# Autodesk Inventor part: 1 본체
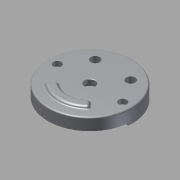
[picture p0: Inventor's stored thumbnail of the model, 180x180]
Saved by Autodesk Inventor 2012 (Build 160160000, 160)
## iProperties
Created: 2015-04
Part Number: 1 본체
Material: Default
Document SubType Name: Modeling
Designer: Owner
Density: 1 g/cm^3
Author: Owner
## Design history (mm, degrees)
sketch "스케치1"
  geometry: C1 r 95 at (0, 0); 1 further point
  constraints: 1 centre point, 1 coincident
  dimensions: "d2" = 190 diameter of C1
extrude "돌출1" new body sketch "스케치1" distance "d3" = 7; taper "d4" = 0 deg
sketch "스케치14"
  geometry: L1 (-82.104, 12)-(-47.117, 12); L2 (47.117, 12)-(82.104, 12); A1 r 95 centre (0, 0) between (-91.763, 24.588) and (91.763, 24.588) reference; A2 r 42 centre (0, 0) between (38.056, 17.769) and (-38.056, 17.769); A3 r 10 centre (47.117, 22) between (38.056, 17.769) and (47.117, 12); A4 r 10 centre (82.104, 22) between (82.104, 12) and (91.763, 24.588); A5 r 10 centre (-47.117, 22) between (-47.117, 12) and (-38.056, 17.769); A6 r 10 centre (-82.104, 22) between (-91.763, 24.588) and (-82.104, 12)
  constraints: 12 point on circle, 12 tangent, 5 centre point, 4 end point, 3 equal radius, 2 horizontal, 1 coincident
  dimensions: "d63" = 84 diameter of A2; "d65" = 20 diameter of A3; "d66" = 12 distance from line of A1.centre L1
extrude "돌출10" join sketch "스케치14" distance "d67" = 7; taper "d68" = 0 deg
sketch "스케치2"
  geometry: L1 (-95, 0)-(95, 0) reference; L2 (95, 0)-(95, -20); L3 (95, -20)-(90, -20); L4 (90, -20)-(90, 0); L5 (0, 0)-(0, -20)
  constraints: 8 end point, 3 perpendicular, 1 horizontal alignment, 1 parallel, 1 point on line
  dimensions: "d5" = 180 diameter of L4 L5; "d6" = 20 distance between parallel lines of L3 L1
revolve "회전1" sketch "스케치2" stored, may be unused: angle "d7" = 90 deg
sketch "스케치13"
  geometry: L1 (0, 0)-(-95, 0); L2 (0, 0)-(-94.638, -8.28); L3 (0, 0)-(95, 0); L4 (0, 0)-(94.638, -8.28); C1 r 90 at (0, 0) reference; C2 r 95 at (0, 0) reference; A1 r 95 centre (0, 0) between (-94.638, -8.28) and (94.638, -8.28); A2 r 90 centre (0, 0) between (-89.658, -7.844) and (89.658, -7.844)
  constraints: 8 end point, 4 point on circle, 2 centre point, 2 coincident, 2 concentric, 2 point on line, 1 collinear, 1 horizontal
  dimensions: "d50" = 5 deg angle of L1 L2; "d51" = 5 deg angle of L4 L3 (= d50); "d52" = 95 distance of L1.start L1.end; "d53" = 95 distance of L1.start L3.end (= d52)
extrude "돌출9" join sketch "스케치13" distance "d54" = 5; taper "d55" = 0 deg
sketch "스케치15"
  geometry: L1 (-47.117, 12)-(-82.104, 12) reference; L2 (-59, -19)-(-59, -14); L3 (-41, -14)-(-41, -19); L4 (41, -19)-(41, -14); L5 (59, -14)-(59, -19); A1 r 90 centre (0, 0) between (-88.811, 14.583) and (88.811, 14.583) reference; A2 r 9 centre (-50, -14) between (-41, -14) and (-59, -14); A3 r 41 centre (0, -19) between (-41, -19) and (41, -19); A4 r 9 centre (50, -14) between (59, -14) and (41, -14); A5 r 59 centre (0, -19) between (-59, -19) and (59, -19)
  constraints: 8 end point, 8 point on circle, 8 tangent, 4 centre point, 4 horizontal alignment, 3 parallel, 1 coincident, 1 perpendicular, 1 vertical alignment
  dimensions: "d69" = 19 distance of A1.centre A3.centre; "d70" = 41 radius of A3; "d71" = 59 radius of A5; "d72" = 5 distance of L2.start L2.end
extrude "돌출11" cut sketch "스케치15" distance "d73" = 7; taper "d74" = 0 deg
sketch "스케치16"
  geometry: C1 r 35 at (0, 0); A1 r 42 centre (0, 0) between (38.056, 17.769) and (-38.056, 17.769) reference
  constraints: 1 centre point, 1 coincident
  dimensions: "d75" = 70 diameter of C1
extrude "돌출12" join sketch "스케치16" distance "d76" = 10; taper "d77" = -10 deg
sketch "스케치17"
  geometry: C1 r 33.237 at (0, 0) reference; C2 r 25 at (0, 0)
  constraints: 1 centre point, 1 coincident
  dimensions: "d78" = 50 diameter of C2
extrude "돌출13" cut sketch "스케치17" distance "d79" = 15; taper "d80" = 0 deg
sketch "스케치18"
  geometry: C1 r 25 at (0, 0) reference; C2 r 11.5 at (0, 0)
  constraints: 1 centre point, 1 coincident
  dimensions: "d81" = 23 diameter of C2
extrude "돌출14" cut sketch "스케치18" stored distance "d82" = 15; taper "d83" = 0 deg
sketch "스케치25"
  geometry: L1 (-47.117, 12)-(-82.104, 12) reference; L2 (-74, 0)-(74, 0); C1 r 35 at (0, 0) reference; C2 r 9 at (-74, 0); C3 r 9 at (74, 0); C4 r 5.5 at (-74, 0); C5 r 5.5 at (74, 0); 1 further point
  constraints: 5 coincident, 4 centre point, 2 end point, 2 equal radius, 1 midpoint, 1 parallel
  dimensions: "d126" = 148 distance of L2.start L2.end; "d127" = 18 diameter of C2; "d128" = 11 diameter of C4
extrude "돌출21" join sketch "스케치25" distance "d129" = 18; taper "d130" = 0 deg
sketch "스케치19"
  geometry: L1 (-74, 0)-(74, 0); C1 r 11.5 at (0, 0) reference; 3 further points
  constraints: 3 coincident, 2 end point, 1 horizontal, 1 midpoint
  dimensions: "d84" = 148 distance of L1.start L1.end
hole "구멍1" sketch "스케치19" at (-74, 0), (74, 0) diameter "d85" = 11; stored, may be unused: countersink angle "d89" = 90 deg, drill point angle "d91" = 0 deg; dims "d86" = 6, "d87" = 18, "d88" = 11, "d90" = 8
sketch "스케치21"
  geometry: L1 (47.117, 12)-(82.104, 12) reference; L2 (-40, 52)-(40, 52); C1 r 15 at (-40, 52); C2 r 15 at (40, 52); A1 r 90 centre (0, 0) between (88.811, 14.583) and (-88.811, 14.583) reference; 1 further point
  constraints: 2 centre point, 2 coincident, 2 end point, 1 equal radius, 1 midpoint, 1 parallel, 1 vertical alignment
  dimensions: "d97" = 52 distance from line of A1.centre L2; "d98" = 80 distance of L2.start L2.end; "d99" = 30 diameter of C1
extrude "돌출16" join sketch "스케치21" distance "d100" = 25; taper "d101" = 0 deg
extrude "돌출17" join sketch "스케치21" distance "d102" = 25; taper "d103" = 0 deg
sketch "스케치22"
  geometry: C1 r 15 at (0, 0) reference; C2 r 10 at (0, 0); C3 r 15 at (80, 0) reference; C4 r 10 at (80, 0); 1 further point
  constraints: 2 centre point, 2 coincident
  dimensions: "d104" = 20 diameter of C2; "d105" = 20 diameter of C4
extrude "돌출18" cut sketch "스케치22" stored distance "d106" = 32; taper "d107" = 0 deg
sketch "스케치23"
  geometry: L1 (6, 13.748)-(6, 8); L2 (6, -8)-(6, -13.748); L3 (-6, -13.748)-(-6, -8); L4 (-6, 8)-(-6, 13.748); A1 r 10 centre (0, 0) between (6, 8) and (6, -8) reference; A2 r 15 centre (0, 0) between (-6, 13.748) and (6, 13.748) reference; 1 further point
  constraints: 8 end point, 8 point on circle, 4 parallel, 2 horizontal alignment, 2 vertical
  dimensions: "d109" = 12 distance between parallel lines of L1 L4; "d110" = 12 distance between parallel lines of L2 L3
extrude "돌출19" cut sketch "스케치23" distance "d111" = 3; taper "d112" = 0 deg
sketch "스케치24"
  geometry: L1 (-13.748, 6)-(-8, 6); L2 (8, 6)-(13.748, 6); L3 (13.748, -6)-(8, -6); L4 (-8, -6)-(-13.748, -6); A1 r 10 centre (0, 0) between (-8, 6) and (8, 6) reference; A2 r 15 centre (0, 0) between (-13.748, 6) and (-13.748, -6) reference; 1 further point
  constraints: 8 end point, 8 point on circle, 4 parallel, 2 horizontal, 2 vertical alignment
  dimensions: "d114" = 12 distance between parallel lines of L2 L3; "d115" = 12 distance between parallel lines of L4 L1
extrude "돌출20" cut sketch "스케치24" distance "d116" = 3; taper "d117" = 0 deg
chamfer "모따기1" distance "d118" = 1; stored, may be unused: second distance "d119" = 2, angle "d120" = 45 deg
fillet "모깎기1" dims "d121" = 3
fillet "모깎기2" dims "d122" = 3
fillet "모깎기3" dims "d123" = 3
fillet "모깎기4" dims "d124" = 3
fillet "모깎기5" dims "d125" = 3
fillet "모깎기6" dims "d131" = 3
chamfer "모따기2" distance "d132" = 1; stored, may be unused: second distance "d133" = 2, angle "d134" = 45 deg
sketch "스케치26"
  geometry: L1 (0, 0)-(-36.062, -36.062); L2 (0, 0)-(36.062, -36.062); L3 (-36.062, -36.062)-(-50.912, -50.912); L4 (36.062, -36.062)-(50.912, -50.912); C1 r 12.5 at (0, 0) reference; A1 r 51 centre (0, 0) between (-36.062, -36.062) and (36.062, -36.062); A2 r 72 centre (0, 0) between (-50.912, -50.912) and (50.912, -50.912)
  constraints: 8 end point, 4 point on circle, 2 centre point, 2 coincident, 2 perpendicular, 1 horizontal alignment
  dimensions: "d136" = 102 diameter of A1; "d137" = 90 deg angle of L2 L1; "d138" = 72 radius of A2
extrude "돌출22" join sketch "스케치26" distance "d139" = 5; taper "d140" = 0 deg
fillet "모깎기7" dims "d141" = 5
fillet "모깎기8" dims "d142" = 5
fillet "모깎기9" dims "d143" = 3
fillet "모깎기10" dims "d144" = 3
fillet "모깎기11" dims "d145" = 1
fillet "모깎기12" dims "d146" = 0.3
node "솔리드1"
other parameters: "d57" = 12, "d64" = 12, "d108" = 12, "d113" = 12, "d135" = 144
